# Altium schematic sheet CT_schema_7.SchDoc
size 274 x 160 mm
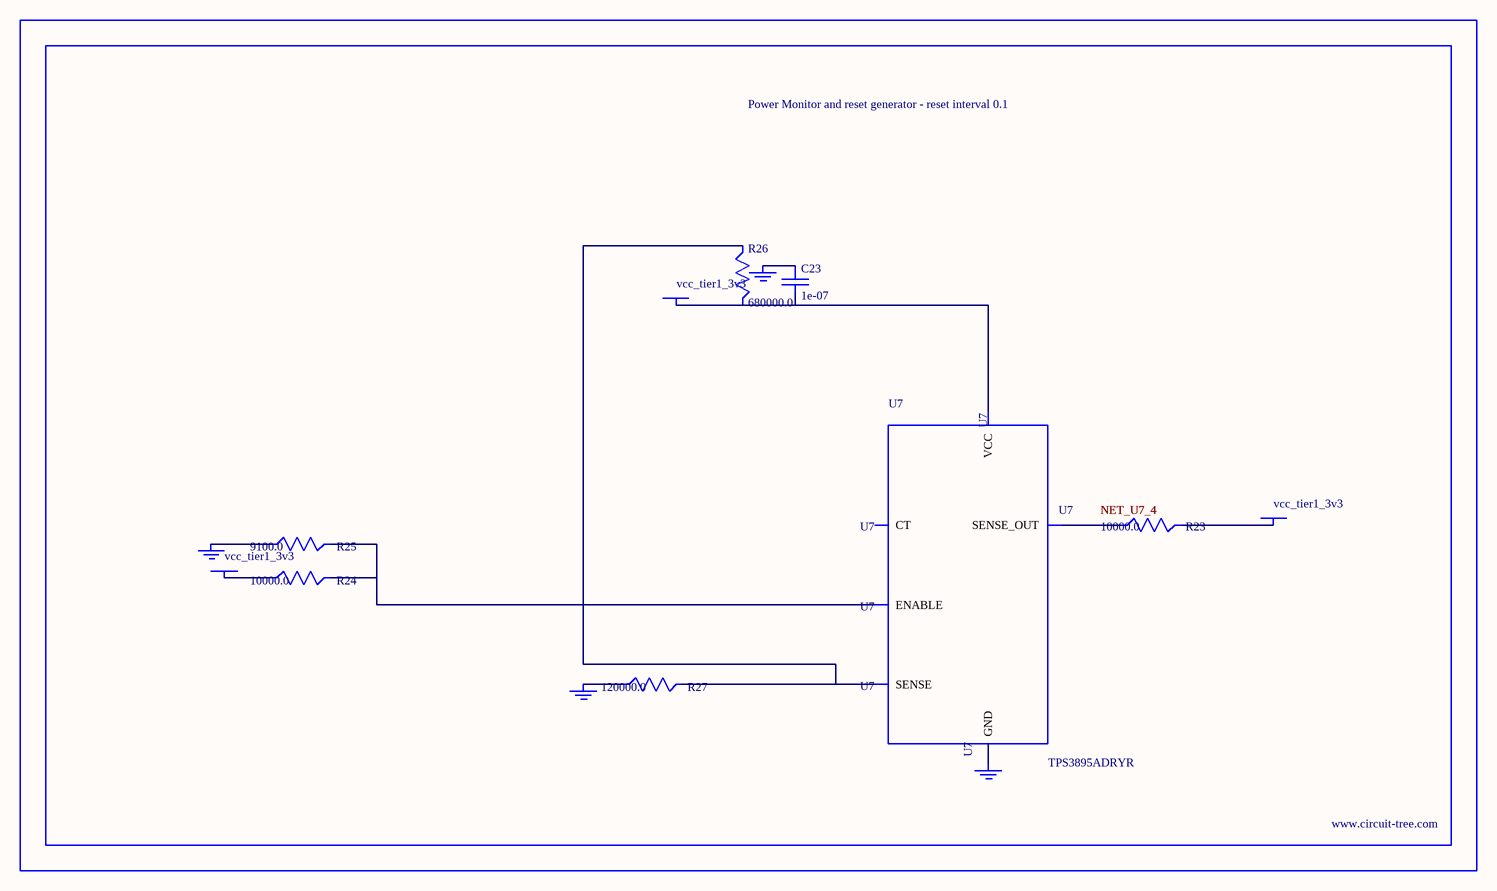
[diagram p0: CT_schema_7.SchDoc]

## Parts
BORDER6  (no value)
C23  1e-07  [C0402]
GND_INSTANCE_6_0  (no value)
GND_INSTANCE_6_1  (no value)
GND_INSTANCE_6_2  (no value)
GND_INSTANCE_6_3  (no value)
POWER_INSTANCE_6_0  vcc_tier1_3v3
POWER_INSTANCE_6_1  vcc_tier1_3v3
POWER_INSTANCE_6_2  vcc_tier1_3v3
R23  10000.0  [R0603]
R24  10000.0  [R0603]
R25  9100.0  [R0603]
R26  680000.0  [R0603]
R27  120000.0  [R0603]
U7  TPS3895ADRYR  [SON-6]

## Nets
NetC23_1: C23.1 GND_INSTANCE_6_2.0(GND)
NetC23_2: C23.2 POWER_INSTANCE_6_2.0(PWR) R26.2 U7.6(VCC)
NetGND_INSTANCE_6_0_0: GND_INSTANCE_6_0.0(GND) R25.1
NetGND_INSTANCE_6_1_0: GND_INSTANCE_6_1.0(GND) R27.1
NetGND_INSTANCE_6_3_0: GND_INSTANCE_6_3.0(GND) U7.2(GND)
NetPOWER_INSTANCE_6_0_0: POWER_INSTANCE_6_0.0(PWR) R24.1
NetPOWER_INSTANCE_6_1_0: POWER_INSTANCE_6_1.0(PWR) R23.2
NetR23_1: R23.1 U7.4(SENSE_OUT)
NetR24_2: R24.2 R25.2 U7.1(ENABLE)
NetR26_1: R26.1 R27.2 U7.3(SENSE)

Not connected (* = marked no-connect by the designer): U7 5(CT)

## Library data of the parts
BORDER6 = BORDER_PAGE6
C23 = C0402C104K3RACTU
GND_INSTANCE_6_0-GND_INSTANCE_6_3 = GND
POWER_INSTANCE_6_0-POWER_INSTANCE_6_2 = PWR
R23 R24 = RC0603JR-0710KL
R25 = RC0603JR-079K1L
R26 = RC0603JR-07680KL
R27 = RC0603JR-07120KL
